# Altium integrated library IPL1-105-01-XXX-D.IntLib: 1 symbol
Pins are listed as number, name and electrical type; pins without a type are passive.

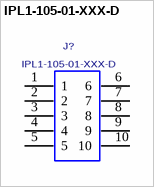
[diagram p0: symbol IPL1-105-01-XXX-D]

## IPL1-105-01-XXX-D
designator J?
0.1 INCH DOUBLE ROW TERMINAL ASSEMBLY, 10 PINS.; MANUFACTURER: SAMTEC
footprint IPL1-105-01-XXX-D
pins: 1, 2, 3, 4, 5, 6, 7, 8, 9, 10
